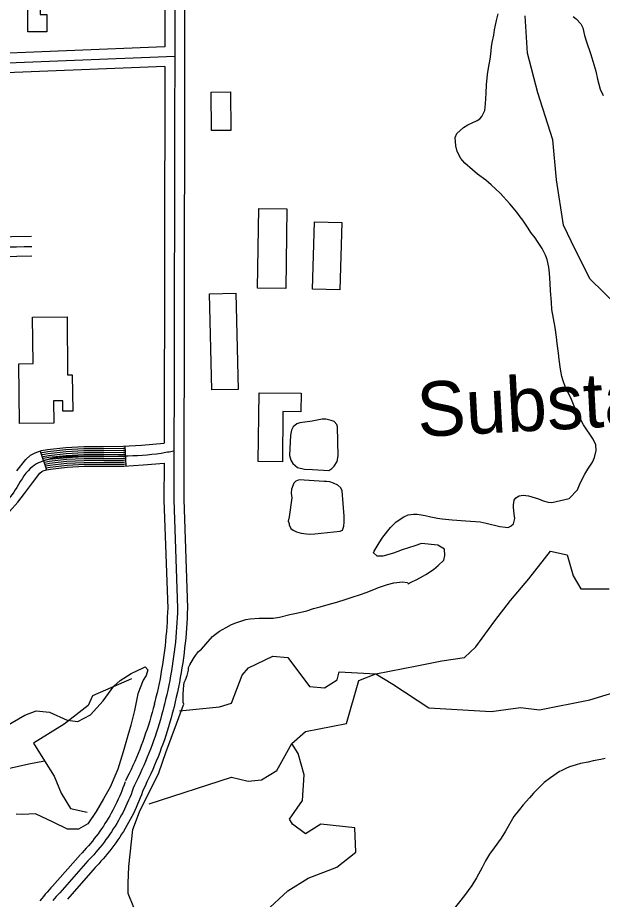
# Model space of a CAD drawing. Extents: x 3313442 to 3351311, y 721974 to 747360.
# Drawn here: x 3325555 to 3326444, y 737443 to 738784 of the extents above; entities that cross this region are included whole.
import ezdxf

# ---------------------------------------------------------------- set-up
doc = ezdxf.new("R2010")
doc.units = 0
for name, color, linetype in [('V-BLDG-OTLN', 7, 'Continuous'), ('V-ROAD-CNTR', 7, 'Continuous'), ('V-SITE-OTLN-IDEN', 7, 'Continuous'), ('V-SITE-VEGE', 7, 'Continuous'), ('V-TOPO-SHOR', 7, 'Continuous')]:
    doc.layers.add(name, color=color, linetype=linetype)

msp = doc.modelspace()

# ---------------------------------------------------------------- linework, layer by layer
at = {"layer": 'V-BLDG-OTLN'}
for points in [[(3325589.1, 738864.8), (3325664.2, 738864.9), (3325664.3, 738809.5), (3325648.4, 738809.5), (3325648.5, 738797.7), (3325589.2, 738797.6), (3325589.2, 738789), (3325599.6, 738789), (3325599.6, 738762.3), (3325570.6, 738762.2), (3325570.5, 738808.4), (3325568.9, 738808.4), (3325568.8, 738845.5), (3325589.2, 738845.5)], [(3325849.6, 738612.3), (3325849.1, 738670.8), (3325878.3, 738671.1), (3325878.9, 738612.6)], [(3325919.8, 738372.4), (3325921.4, 738493.9), (3325964.1, 738493.3), (3325962.5, 738371.9)], [(3326002.9, 738371.2), (3326006, 738473.6), (3326047.8, 738472.3), (3326044.7, 738369.9)], [(3325850.2, 738217.8), (3325846.7, 738364.2), (3325886.5, 738365.1), (3325890, 738218.7)], [(3325557.9, 738166.8), (3325557.1, 738257.6), (3325578.5, 738257.8), (3325577.8, 738328.4), (3325630.2, 738328.9), (3325631, 738240.9), (3325638.1, 738241), (3325638.7, 738185.6), (3325623.7, 738185.4), (3325623.5, 738201.3), (3325609.5, 738201.2), (3325609.8, 738167.3)], [(3325920.6, 738109.2), (3325921.9, 738213.6), (3325985.9, 738212.8), (3325985.5, 738184.7), (3325958.3, 738185.1), (3325957.3, 738108.7)]]:
    msp.add_lwpolyline(points, close=True, dxfattribs=at)
at = {"layer": 'V-ROAD-CNTR'}
for p, q in [((3325589.1, 738124.8), (3325598.8, 738096.4)), ((3325717.8, 738132.2), (3325719.4, 738102.3))]:
    msp.add_line(p, q, dxfattribs=at)
for points in [[(3325794.9, 739304.2), (3325792.4, 738050.7)], [(3325779.8, 739288.7), (3325778.7, 738739.5)], [(3325809.8, 739289.6), (3325807.4, 738050.7)], [(3325778.7, 738739.5), (3325329.9, 738721.6)], [(3325793.7, 738725.1), (3323837.2, 738647)], [(3325778.7, 738709.5), (3324306.8, 738650.7)], [(3325778.7, 738709.5), (3325777.6, 738136.8)], [(3325576.1, 738451.2), (3325484.3, 738449.5)], [(3325576.7, 738421.2), (3325484.9, 738419.5), (3325393.1, 738417.6), (3325250.1, 738414.4), (3325107.1, 738410.8), (3325016.9, 738407.4), (3324926.8, 738403.3), (3324915.1, 738402.6), (3324904.1, 738401.8), (3324900.3, 738401.1), (3324898.4, 738400.5), (3324894.5, 738398.6), (3324890.2, 738395.7), (3324885.9, 738392.1), (3324883.4, 738389.6), (3324882.6, 738388.4), (3324881.8, 738387), (3324881.6, 738385.7), (3324883.3, 738358.3), (3324885.5, 738328.9), (3324887.7, 738263.7), (3324889.7, 738198.8), (3324890.4, 738170.9)], [(3325553.6, 738094.7), (3325567.3, 738112), (3325574.8, 738118.4), (3325581.7, 738122.2), (3325591.3, 738125.5), (3325600.5, 738127.2), (3325628.1, 738130.2), (3325655.5, 738131.7), (3325685.7, 738131.8), (3325715.3, 738132.1), (3325743.3, 738133.6), (3325777.6, 738136.8)], [(3325590.1, 738121.9), (3325592.1, 738122.6), (3325600.9, 738124.3), (3325628.3, 738127.2), (3325655.6, 738128.7), (3325685.8, 738128.8), (3325715.4, 738129.1), (3325717.9, 738129.2)], [(3325591.1, 738119.1), (3325592.8, 738119.7), (3325601.4, 738121.3), (3325628.6, 738124.3), (3325655.7, 738125.7), (3325685.8, 738125.8), (3325715.5, 738126.1), (3325718.1, 738126.2)], [(3325592, 738116.2), (3325593.6, 738116.8), (3325601.8, 738118.3), (3325628.8, 738121.3), (3325655.7, 738122.7), (3325685.8, 738122.8), (3325715.6, 738123.1), (3325718.3, 738123.3)], [(3325593, 738113.4), (3325594.4, 738113.9), (3325602.3, 738115.4), (3325629, 738118.3), (3325655.8, 738119.7), (3325685.8, 738119.8), (3325715.7, 738120.1), (3325718.4, 738120.3)], [(3325594, 738110.6), (3325595.1, 738111), (3325602.7, 738112.4), (3325629.3, 738115.3), (3325655.9, 738116.7), (3325685.8, 738116.8), (3325715.8, 738117.1), (3325718.6, 738117.3)], [(3325594.9, 738107.7), (3325595.9, 738108.1), (3325603.1, 738109.4), (3325629.5, 738112.3), (3325656, 738113.7), (3325685.9, 738113.8), (3325715.9, 738114.1), (3325718.7, 738114.3)], [(3325595.9, 738104.9), (3325596.7, 738105.1), (3325603.6, 738106.5), (3325629.8, 738109.3), (3325656.1, 738110.7), (3325685.9, 738110.8), (3325716, 738111.1), (3325718.9, 738111.3)], [(3325596.9, 738102.1), (3325597.4, 738102.2), (3325604, 738103.5), (3325630, 738106.3), (3325656.2, 738107.7), (3325685.9, 738107.8), (3325716.1, 738108.1), (3325719.1, 738108.3)], [(3325542.9, 738033.1), (3325555.3, 738047.2), (3325565.6, 738060.5), (3325577.4, 738076.5), (3325589, 738091.1), (3325591.9, 738093.6), (3325593.9, 738094.7), (3325599, 738096.4), (3325604.9, 738097.5), (3325630.5, 738100.3), (3325656.3, 738101.7), (3325685.9, 738101.8), (3325716.3, 738102.1), (3325745.6, 738103.7), (3325777.5, 738106.7)], [(3325597.9, 738099.2), (3325598.2, 738099.3), (3325604.5, 738100.5), (3325630.2, 738103.3), (3325656.2, 738104.7), (3325685.9, 738104.8), (3325716.2, 738105.1), (3325719.2, 738105.3)], [(3325777.5, 738106.7), (3325777.4, 738050.8)], [(3325777.4, 738050.2), (3325783.1, 737885.6)], [(3325792.4, 738050.7), (3325798.1, 737886.1)], [(3325807.4, 738051.3), (3325813, 737886.7)], [(3325783.1, 737886.6), (3325782.8, 737879.3), (3325782.5, 737872.1), (3325782.1, 737864.8), (3325781.7, 737857.6), (3325781.1, 737850.4), (3325780.5, 737843.2), (3325779.8, 737836), (3325779, 737828.8), (3325778.1, 737821.6), (3325777.2, 737814.4), (3325776.2, 737807.2), (3325775.1, 737800.1), (3325773.9, 737792.9), (3325772.7, 737785.8), (3325771.4, 737778.7), (3325770, 737771.6), (3325768.5, 737764.5), (3325766.9, 737757.4), (3325765.3, 737750.4), (3325763.6, 737743.3), (3325762.7, 737739.9)], [(3325798.1, 737886.1), (3325797.8, 737878.7), (3325797.5, 737871.4), (3325797.1, 737864), (3325796.6, 737856.6), (3325796.1, 737849.2), (3325795.4, 737841.8), (3325794.7, 737834.4), (3325793.9, 737827.1), (3325793, 737819.7), (3325792.1, 737812.4), (3325791, 737805.1), (3325789.9, 737797.7), (3325788.7, 737790.4), (3325787.5, 737783.1), (3325786.1, 737775.9), (3325784.7, 737768.6), (3325783.2, 737761.3), (3325781.6, 737754.1), (3325779.9, 737746.9), (3325778.2, 737739.7), (3325777.3, 737736.2)], [(3325813, 737885.7), (3325812.8, 737878.2), (3325812.5, 737870.6), (3325812.1, 737863.1), (3325811.6, 737855.5), (3325811, 737848), (3325810.4, 737840.4), (3325809.6, 737832.9), (3325808.8, 737825.4), (3325807.9, 737817.9), (3325806.9, 737810.4), (3325805.9, 737802.9), (3325804.7, 737795.4), (3325803.5, 737787.9), (3325802.2, 737780.5), (3325800.8, 737773), (3325799.4, 737765.6), (3325797.8, 737758.2), (3325796.2, 737750.8), (3325794.5, 737743.4), (3325792.7, 737736.1), (3325791.8, 737732.6)], [(3325762.8, 737740), (3325761.1, 737733.5), (3325759.4, 737727.1), (3325757.6, 737720.8), (3325755.7, 737714.5), (3325753.7, 737708.2), (3325751.7, 737701.9), (3325749.6, 737695.6), (3325747.4, 737689.4), (3325745.2, 737683.2), (3325742.9, 737677), (3325740.5, 737670.9), (3325738, 737664.8), (3325735.5, 737658.7), (3325732.9, 737652.6), (3325730.2, 737646.6), (3325727.4, 737640.6), (3325724.6, 737634.6), (3325721.7, 737628.7), (3325719, 737623.4)], [(3325777.3, 737736.2), (3325775.6, 737729.6), (3325773.8, 737723.1), (3325772, 737716.6), (3325770, 737710.1), (3325768, 737703.6), (3325766, 737697.2), (3325763.8, 737690.8), (3325761.6, 737684.4), (3325759.3, 737678), (3325756.9, 737671.7), (3325754.4, 737665.4), (3325751.9, 737659.1), (3325749.3, 737652.8), (3325746.6, 737646.6), (3325743.8, 737640.4), (3325741, 737634.3), (3325738.1, 737628.1), (3325735.1, 737622), (3325732.5, 737616.7)], [(3325791.8, 737732.4), (3325790.1, 737725.8), (3325788.3, 737719.1), (3325786.4, 737712.4), (3325784.4, 737705.7), (3325782.3, 737699.1), (3325780.2, 737692.5), (3325778, 737685.9), (3325775.7, 737679.3), (3325773.3, 737672.8), (3325770.9, 737666.3), (3325768.4, 737659.8), (3325765.8, 737653.4), (3325763.1, 737647), (3325760.3, 737640.6), (3325757.5, 737634.2), (3325754.6, 737627.9), (3325751.6, 737621.6), (3325748.6, 737615.4), (3325745.9, 737609.9)], [(3325718.3, 737621.6), (3325716.7, 737617.1), (3325715.1, 737612.7), (3325713.4, 737608.3), (3325711.7, 737603.9), (3325709.8, 737599.6), (3325707.9, 737595.3), (3325706, 737591.1), (3325703.9, 737586.8), (3325701.8, 737582.7), (3325699.7, 737578.5), (3325697.4, 737574.4), (3325695.1, 737570.3), (3325692.7, 737566.2), (3325690.3, 737562.2), (3325687.8, 737558.3), (3325685.3, 737554.3), (3325682.6, 737550.5), (3325679.9, 737546.6), (3325677.2, 737542.8), (3325674.4, 737539.1), (3325671.5, 737535.4), (3325668.6, 737531.7), (3325665.6, 737528.1), (3325662.5, 737524.5), (3325659.4, 737521), (3325656.3, 737517.6), (3325653, 737514.1), (3325650.9, 737512)], [(3325732.5, 737616.7), (3325730.8, 737612), (3325729.1, 737607.4), (3325727.4, 737602.8), (3325725.5, 737598.2), (3325723.6, 737593.7), (3325721.6, 737589.2), (3325719.5, 737584.7), (3325717.4, 737580.2), (3325715.2, 737575.8), (3325712.9, 737571.4), (3325710.5, 737567.1), (3325708.1, 737562.8), (3325705.6, 737558.6), (3325703.1, 737554.3), (3325700.4, 737550.2), (3325697.7, 737546), (3325695, 737542), (3325692.2, 737537.9), (3325689.3, 737533.9), (3325686.3, 737530), (3325683.3, 737526.1), (3325680.2, 737522.2), (3325677, 737518.4), (3325673.8, 737514.7), (3325670.6, 737511), (3325667.2, 737507.4), (3325663.9, 737503.8), (3325661.7, 737501.6)], [(3325746.6, 737611.7), (3325745, 737607), (3325743.2, 737602.1), (3325741.3, 737597.3), (3325739.4, 737592.5), (3325737.4, 737587.7), (3325735.3, 737583), (3325733.1, 737578.3), (3325730.9, 737573.6), (3325728.5, 737569), (3325726.1, 737564.4), (3325723.7, 737559.9), (3325721.1, 737555.3), (3325718.5, 737550.9), (3325715.8, 737546.5), (3325713.1, 737542.1), (3325710.2, 737537.7), (3325707.3, 737533.5), (3325704.4, 737529.2), (3325701.3, 737525), (3325698.2, 737520.9), (3325695.1, 737516.8), (3325691.8, 737512.8), (3325688.5, 737508.8), (3325685.2, 737504.8), (3325681.7, 737501), (3325678.2, 737497.1), (3325674.7, 737493.4), (3325672.5, 737491.1)], [(3325650.4, 737511.4), (3325608, 737463.1)], [(3325661.7, 737501.6), (3325619.3, 737453.2)], [(3325673, 737491.7), (3325630.6, 737443.3)], [(3325608.5, 737463.6), (3325605.6, 737460.6), (3325602.7, 737457.5), (3325599.8, 737454.2), (3325597, 737451), (3325594.3, 737447.6), (3325591.6, 737444.2), (3325589, 737440.8)], [(3325619.3, 737453.2), (3325616.5, 737450.3), (3325613.8, 737447.4), (3325611.1, 737444.4), (3325608.5, 737441.3)]]:
    msp.add_lwpolyline(points, dxfattribs=at)
msp.add_spline([(3325792.5, 738124.8), (3325773.1, 738121.3), (3325715.8, 738117.1), (3325655.9, 738116.7), (3325602.7, 738112.4), (3325578.1, 738101.6), (3325553.6, 738069.5), (3325532.8, 738044.3), (3325506.4, 738034.6), (3325482.9, 738032), (3325456.2, 738010.8), (3325447.4, 737989.3), (3325436.4, 737967.2), (3325398.5, 737951.9), (3325290.4, 737956.7), (3325211.2, 737952), (3325071.1, 737951.6), (3324987.3, 737945.1), (3324942.5, 737944.6), (3324918.7, 737947.3), (3324900.8, 737968), (3324886.8, 737992), (3324879.7, 738024.1), (3324876.9, 738111.7), (3324874.7, 738198.4), (3324870.5, 738328.1), (3324866.6, 738386.5), (3324881.2, 738407.7), (3324902.2, 738416.7), (3324926, 738418.3), (3325106.6, 738425.8), (3325392.8, 738432.6), (3325576.4, 738436.2)], degree=3, dxfattribs=at)
at = {"layer": 'V-SITE-VEGE'}
for points in [[(3326156.7, 738028.9), (3326162.4, 738029), (3326174.6, 738026.8), (3326182.9, 738024.9), (3326193.1, 738023), (3326200.2, 738021.9), (3326215.6, 738020.3), (3326236.1, 738019), (3326257.7, 738017.2), (3326266.9, 738015.3), (3326287.7, 738010.1), (3326296.5, 738009), (3326300.5, 738008.8), (3326305, 738011.1), (3326308.7, 738014.2), (3326310.6, 738022.5), (3326309.7, 738028.7), (3326308.5, 738039.5), (3326308.4, 738042.9), (3326309.8, 738050.1), (3326312.3, 738053.5), (3326317.4, 738056.7), (3326323.1, 738057.6), (3326331.6, 738056.8), (3326346.8, 738052.1), (3326353.6, 738049.3), (3326361.3, 738047.4), (3326367, 738046.5), (3326393.1, 738052.7), (3326405.8, 738065.9), (3326409.7, 738076.2), (3326417, 738089.9), (3326421.8, 738097.3), (3326428.8, 738107.9), (3326431.6, 738115), (3326434.3, 738125.6), (3326433.7, 738134.1), (3326429.6, 738142.9), (3326415, 738165), (3326411.5, 738171.2), (3326407.4, 738180), (3326404, 738185.6), (3326396.7, 738203.2), (3326391, 738214.8), (3326387.8, 738221.6), (3326384, 738231.8), (3326382.2, 738238.1), (3326380.2, 738249.2), (3326378, 738264.2), (3326377.1, 738273.6), (3326375, 738288.4), (3326374.1, 738298.3), (3326372, 738312.8), (3326366.9, 738340.3), (3326366.3, 738351.4), (3326364.7, 738368.8), (3326364.3, 738380.1), (3326363.1, 738395.2), (3326362.1, 738404.6), (3326360, 738416.2), (3326357.4, 738423), (3326352.2, 738432.7), (3326345.3, 738443.7), (3326341.6, 738449.1), (3326335, 738457.3), (3326330.9, 738463.8), (3326325.8, 738471.4), (3326322.9, 738475.9), (3326318.6, 738481.3), (3326313.7, 738488.4), (3326303, 738501.1), (3326288.4, 738517.2), (3326274.9, 738529.6), (3326266.4, 738536.9), (3326254.1, 738545.9), (3326246.3, 738552.4), (3326234.6, 738562.8), (3326228.8, 738569.6), (3326222.8, 738580.6), (3326221, 738589.2), (3326219.8, 738601.7), (3326222.6, 738607.9), (3326232.7, 738617.1), (3326239.2, 738621.2), (3326245.7, 738624.3), (3326253.4, 738627.5), (3326257.4, 738630.1), (3326260.7, 738633.6), (3326265.2, 738643), (3326266.3, 738652.7), (3326267.3, 738669.2), (3326267.8, 738681.7), (3326269.3, 738697.6), (3326270.4, 738707.3), (3326273.1, 738720.7), (3326274.2, 738728.7), (3326275.3, 738739.5), (3326276.3, 738746.3), (3326278.8, 738757.4), (3326279.9, 738765.4), (3326282.9, 738779.9)], [(3326282.9, 738779.9), (3326285.4, 738789.6)], [(3326399.2, 738786), (3326404, 738782), (3326410.9, 738774.4), (3326413.8, 738768.5), (3326416.5, 738757.1), (3326419.7, 738747.2), (3326425.8, 738729.6), (3326427.5, 738723.1), (3326433.7, 738702.6)], [(3326433.7, 738702.6), (3326436.1, 738690.7), (3326440.4, 738675.4), (3326444.8, 738665.8)], [(3325740, 737409.4), (3325723, 737451.9), (3325722.9, 737467.8), (3325724.2, 737493), (3325730.1, 737549.2), (3325740.1, 737576.1), (3325769.6, 737635.7), (3325780.4, 737666.6), (3325796.6, 737710.2), (3325805.8, 737734.7), (3325806.6, 737737.2), (3325807.6, 737740), (3325806.6, 737742.6), (3325806.5, 737750.5), (3325806.5, 737754.5), (3325807.3, 737763.3), (3325808.3, 737773), (3325810, 737777), (3325812.5, 737783.6), (3325814.5, 737791.5), (3325814.7, 737794.1), (3325814.7, 737795.5), (3325816.7, 737799.8), (3325822.3, 737809.2), (3325825.1, 737813.8), (3325829.9, 737819.8), (3325834.7, 737823.8), (3325840.9, 737831.3), (3325851.3, 737843), (3325855.8, 737846.2), (3325862, 737850.8), (3325866.6, 737853.7), (3325871.7, 737856.6), (3325880.2, 737860.9), (3325886.7, 737863.5), (3325892.6, 737865.5), (3325901.7, 737868.5), (3325908.5, 737869.7), (3325921.9, 737870.6), (3325943.5, 737870.8), (3325953.2, 737872.3), (3325968.5, 737876.4), (3325979, 737878.2), (3325994.6, 737882), (3326004.5, 737885.2), (3326014.8, 737888.1), (3326030.4, 737892.3), (3326040, 737895.2), (3326054.5, 737899.8), (3326063.6, 737902.5), (3326076, 737906.8), (3326084.8, 737909.8), (3326096.5, 737914.1), (3326103.3, 737917.3), (3326116.9, 737922), (3326126.5, 737924.3), (3326139.9, 737926.1), (3326147.6, 737925.1), (3326148.7, 737923.1), (3326153.2, 737925.4), (3326161.7, 737929.4), (3326171.9, 737934.9), (3326175.6, 737937.2), (3326186.9, 737945), (3326194, 737950.7), (3326202.5, 737959.1), (3326204.4, 737965.9), (3326203.7, 737975.6), (3326193.7, 737982), (3326168.7, 737984.4), (3326158.5, 737980.9), (3326139.5, 737974.8), (3326126.4, 737969.5), (3326110, 737964.8), (3326101.5, 737964.8), (3326096, 737969.9), (3326096.8, 737972.7), (3326104.4, 737985.3), (3326110, 737994.1), (3326121.9, 738008.7), (3326130.3, 738017.3), (3326141.9, 738025.1), (3326148.4, 738028), (3326156.7, 738028.9)], [(3325526.8, 737700.7), (3325565.8, 737723.4), (3325583.4, 737730), (3325603.7, 737727.6), (3325630.3, 737715.4), (3325646.3, 737713.5), (3325665.9, 737723.7), (3325685.2, 737745.1), (3325701.2, 737767.3), (3325710.8, 737775.9), (3325727.8, 737786.7), (3325745.7, 737795.4), (3325748.6, 737796.9), (3325753.1, 737792.2), (3325750.2, 737783.4), (3325745.8, 737776.5), (3325737.8, 737755.6), (3325732.4, 737730.5), (3325727.3, 737708.1), (3325720.4, 737685), (3325715.6, 737667.3), (3325707.3, 737641), (3325695.5, 737613.5), (3325685.6, 737595.8), (3325674.3, 737576.8), (3325661.5, 737557.9), (3325647.7, 737549.8), (3325630.6, 737549.6), (3325608.8, 737560.3), (3325582.4, 737573.1), (3325562.1, 737572), (3325553, 737572.5)], [(3326447.8, 737657.3), (3326441.2, 737655.8), (3326429.6, 737653.7), (3326421.9, 737651.7), (3326410.6, 737649.6), (3326403.8, 737647.8), (3326393.8, 737644.6), (3326388.2, 737642.3), (3326381.1, 737638.5), (3326378.5, 737637.4), (3326365, 737627.9), (3326355.3, 737620.7), (3326348.6, 737614.1), (3326339, 737604.4), (3326333.1, 737597.5), (3326323.5, 737586.9), (3326317.6, 737580), (3326309.1, 737569.1), (3326296.5, 737546.6), (3326290, 737536.3), (3326279.1, 737521.4), (3326272.3, 737511.7), (3326266.1, 737501.7), (3326261.1, 737491.7), (3326252.4, 737475.7), (3326245.1, 737464), (3326234.1, 737448.8), (3326217, 737427.3)]]:
    msp.add_lwpolyline(points, dxfattribs=at)
at = {"layer": 'V-TOPO-SHOR'}
for points in [[(3326465.5, 738346.9), (3326425, 738386.2), (3326402.4, 738431.2), (3326384.6, 738468.5), (3326374.2, 738537.3), (3326368.5, 738598.2), (3326345.5, 738669.9), (3326329.7, 738729.9), (3326326.5, 738787)], [(3326021.1, 738078.6), (3325983.1, 738081.1), (3325977.7, 738078.9), (3325974.9, 738076), (3325972, 738069.7), (3325971.4, 738067), (3325970.7, 738060.9), (3325971.8, 738053.6), (3325967.9, 738025.1), (3325966.4, 738018.4), (3325967.6, 738014.7), (3325967.8, 738012.5), (3325970, 738007.1), (3325973.7, 738004.8), (3325978.7, 738002.2), (3325985.9, 737999.9), (3325998.1, 737998.4), (3326006.7, 737999.2), (3326045.4, 738002.8), (3326048.7, 738004.8), (3326050.8, 738010.6), (3326051.5, 738016.8), (3326051.5, 738025.9), (3326048, 738064.6), (3326046.2, 738069.2), (3326041.5, 738073.1), (3326035.2, 738076), (3326029.4, 738078), (3326024.6, 738078.5), (3326021.1, 738078.6), (3326021.1, 738078.6)], [(3325801.1, 737730), (3325862, 737735.7), (3325879.9, 737741.4), (3325896.5, 737783.9), (3325905.7, 737795), (3325943, 737812.8), (3325965.8, 737810.8), (3325998.5, 737766.7), (3326021.3, 737764.7), (3326040.6, 737776.8), (3326043.6, 737789.3), (3326099.2, 737786.3), (3326161.6, 737798.2), (3326199.9, 737805.8), (3326234.2, 737811.1), (3326251.2, 737827), (3326280.4, 737866.6), (3326304.1, 737897.4), (3326331.8, 737930.7), (3326364.8, 737972.7), (3326390, 737966.9), (3326399.1, 737934.9), (3326411.1, 737915.5), (3326454.2, 737915.4)], [(3325754.7, 737588.4), (3325880.1, 737628.7), (3325905.2, 737622.8), (3325925.6, 737624.7), (3325948.8, 737639.2), (3325971.7, 737680.2), (3325992.5, 737698.5), (3326055, 737710.5), (3326073.5, 737775.7), (3326099.2, 737786.3), (3326125.3, 737770.2), (3326179.8, 737734.3), (3326274.6, 737728.7), (3326319.2, 737734.9), (3326348.2, 737731.4), (3326424.7, 737746.7), (3326474.5, 737761.5)], [(3325727.9, 737778.6), (3325668.8, 737752.7), (3325662, 737737.7), (3325625.6, 737709.7), (3325579.1, 737680.8), (3325579.1, 737680.8), (3325596, 737653.7)], [(3325931.8, 737424.4), (3325965.7, 737456.2), (3325996.7, 737475.5), (3326040.3, 737491.8), (3326068.9, 737515), (3326067.6, 737551.7), (3326015.8, 737557.2), (3325992.6, 737542.8), (3325972.8, 737557.3), (3325968, 737565.1), (3325987.9, 737593.6), (3325990.4, 737632.7), (3325981.3, 737664.7), (3325971.7, 737680.2)], [(3325195, 737512.1), (3325244.9, 737527), (3325296.2, 737548.1), (3325315.6, 737560.2), (3325344.6, 737556.7), (3325375.1, 737559.5), (3325422.6, 737578.2), (3325447.8, 737615.4), (3325529.6, 737639.4), (3325571.8, 737649.4), (3325596, 737653.7), (3325610.4, 737630.4), (3325621, 737604.8), (3325628.2, 737593.1), (3325635.4, 737581.5), (3325660.6, 737575.6)]]:
    msp.add_lwpolyline(points, dxfattribs=at)
msp.add_lwpolyline([(3326002.6, 738170.5), (3325983.8, 738167.9), (3325979.2, 738166.2), (3325973.9, 738161.8), (3325971.4, 738156.8), (3325969.5, 738148.8), (3325968, 738118.3), (3325970.4, 738110.8), (3325973.5, 738105.8), (3325980.5, 738100), (3325991.2, 738097.5), (3326002.9, 738096.8), (3326027.8, 738095.2), (3326032.7, 738098.3), (3326036.3, 738101.7), (3326040.8, 738109), (3326042.2, 738117.8), (3326041.2, 738161.5), (3326040, 738165.3), (3326036.1, 738169.7), (3326031.6, 738171.5), (3326023.6, 738173.3), (3326018, 738173.3)], close=True, dxfattribs=at)

# ---------------------------------------------------------------- texts
at = {"layer": 'V-SITE-OTLN-IDEN'}
msp.add_text('Substation', height=83, rotation=3.0566, dxfattribs=at).set_placement((3326163.9, 738146.3))

doc.saveas('drawing.dxf')
